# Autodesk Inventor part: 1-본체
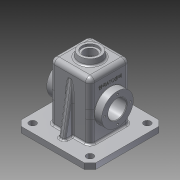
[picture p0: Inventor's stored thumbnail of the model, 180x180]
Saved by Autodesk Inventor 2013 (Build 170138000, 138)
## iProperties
Created: 2016-02
Part Number: 1-본체
Material: 알루미늄 6061
Document SubType Name: Modeling
Designer: max6
Density: 2.40731 g/cm^3
Mass: 798.498 g
Surface Area: 993.367 cm^2
Volume: 331.697 cm^3
Author: max6
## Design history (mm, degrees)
sketch "스케치1"
  geometry: L1 (-65, 65)-(65, 65); L2 (65, 65)-(65, -65); L3 (65, -65)-(-65, -65); L4 (-65, -65)-(-65, 65); 3 further points
  constraints: 8 end point, 2 midpoint, 2 parallel, 1 horizontal, 1 horizontal alignment, 1 perpendicular, 1 vertical alignment
  dimensions: "d0" = 130 distance between parallel lines of L2 L4; "d2" = 130 distance between parallel lines of L3 L1
extrude "돌출1" new body sketch "스케치1" distance "d3" = 10; taper "d4" = 0 deg
sketch "스케치2"
  geometry: L1 (-35, 35)-(35, 35); L2 (35, 35)-(35, -35); L3 (35, -35)-(-35, -35); L4 (-35, -35)-(-35, 35); 3 further points
  constraints: 8 end point, 2 midpoint, 2 parallel, 1 horizontal, 1 horizontal alignment, 1 perpendicular, 1 vertical alignment
  dimensions: "d5" = 70 distance between parallel lines of L2 L4; "d7" = 70 distance between parallel lines of L3 L1
extrude "돌출2" join sketch "스케치2" distance "d8" = 100; taper "d9" = 0 deg
feature "쉘1" dims "d14" = 10, "d15" = 5
sketch "스케치5"
  geometry: C1 r 20 at (0, 0); 1 further point
  constraints: 1 centre point, 1 coincident
  dimensions: "d17" = 40 diameter of C1
extrude "돌출4" join sketch "스케치5" distance "d19" = 10; taper "d20" = 0 deg
sketch "스케치6"
  geometry: L1 (-35, 10)-(-35, 110) reference; L2 (-30, 0)-(-30, 105) reference; L3 (-23, 55)-(-23, 75.5); L4 (-23, 75.5)-(-30, 82.5); L5 (-30, 82.5)-(-48, 82.5); L6 (-48, 82.5)-(-48, 55); L7 (-48, 55)-(-23, 55); L8 (-65, 0)-(65, 0) reference; 1 further point
  constraints: 10 end point, 2 perpendicular, 1 parallel, 1 point on line
  dimensions: "d21" = 55 diameter of L5 L7; "d23" = 13 distance between parallel lines of L1 L6; "d25" = 7 distance between parallel lines of L2 L3; "d26" = 135 deg angle of L2 L4; "d27" = 55 distance from line of L6.end L8
revolve "회전1" sketch "스케치6" stored, may be unused: angle "d28" = 90 deg
feature "면 기울기2" dims angle "d29" = 10 deg
sketch "스케치7"
  geometry: C1 r 18.237 at (0, 0) reference; 1 further point
  constraints: 1 coincident
hole "구멍1" sketch "스케치7" at (0, 0) diameter "d30" = 21; stored, may be unused: countersink angle "d34" = 90 deg, drill point angle "d36" = 118 deg; dims "d31" = 6, "d32" = 28, "d33" = 4, "d35" = 8
sketch "스케치8"
  geometry: C1 r 27.5 at (0, 0) reference; C2 r 16 at (0, 0); 1 further point
  constraints: 1 centre point, 1 coincident
  dimensions: "d37" = 32 diameter of C2
extrude "돌출5" cut sketch "스케치8" distance "d40" = 25; taper "d41" = 0 deg
sketch "스케치9"
  geometry: C1 r 16 at (0, 0) reference; 2 further points
  constraints: 1 vertical alignment
  dimensions: "d42" = 22.5 distance of point (0, 22.5) C1.centre
hole "구멍2" sketch "스케치9" at (0, 22.5) diameter "d43" = 3.242; stored, may be unused: countersink angle "d47" = 90 deg, drill point angle "d49" = 118 deg; dims "d44" = 8, "d45" = 28, "d46" = 4, "d48" = 10
sketch "스케치10"
  geometry: L1 (35, 10)-(35, 110) reference; L2 (65, 10)-(-65, 10) reference; L3 (35, 95.069)-(50, 10); L4 (65, 0)-(65, 10) reference; 1 further point
  constraints: 2 end point, 2 point on line
  dimensions: "d53" = 15 distance from line of L3.end L4; "d54" = 10 deg angle of L3 L4
extrude "돌출6" join sketch "스케치10" stored distance "d55" = 10; taper "d56" = 0 deg
fillet "모깎기2" dims "d58" = 3
fillet "모깎기3" dims "d59" = 0.5
fillet "모깎기4" dims "d60" = 8
fillet "모깎기5" dims "d61" = 8
fillet "모깎기7" dims "d63" = 3
fillet "모깎기8" dims "d64" = 3
chamfer "모따기1" distance "d65" = 10; stored, may be unused: second distance "d66" = 2, angle "d67" = 45 deg
fillet "모깎기9" dims "d70" = 3
fillet "모깎기10" dims "d71" = 3
chamfer "모따기2" distance "d72" = 1; stored, may be unused: second distance "d73" = 2, angle "d74" = 45 deg
sketch "스케치13"
  geometry: C1 r 6 at (50, 50); 1 further point
  constraints: 1 centre point
  dimensions: "d75" = 50 horizontal distance of C1.centre point (0, 0); "d76" = 50 horizontal distance of point (0, 0) C1.centre; "d78" = 12 diameter of C1
extrude "돌출7" cut sketch "스케치13" distance "d79" = 10; taper "d80" = 0 deg
sketch "스케치14"
  geometry: L1 (-65, 18.237)-(-65, -18.237) reference; L2 (-7.416, 35)-(-47, 35) reference; 2 further points
  constraints: 1 other
  dimensions: "d87" = 30 distance from line of L1 point (-35, 0); "d88" = 35 distance from line of L2 point (-35, 0)
feature "엠보싱1" sketch "스케치14" dims "d0" = 130, "d2" = 130, "d17" = 40, "d89" = 0.5, "d90" = 0
fillet "모깎기11" dims "d91" = 0.5
node "솔리드1"
pattern_circular "원형 패턴1" dims angle "d51" = 360 deg
mirror "대칭2"
mirror "대칭4"
pattern_linear "직사각형 패턴1" dims "d83" = 100
